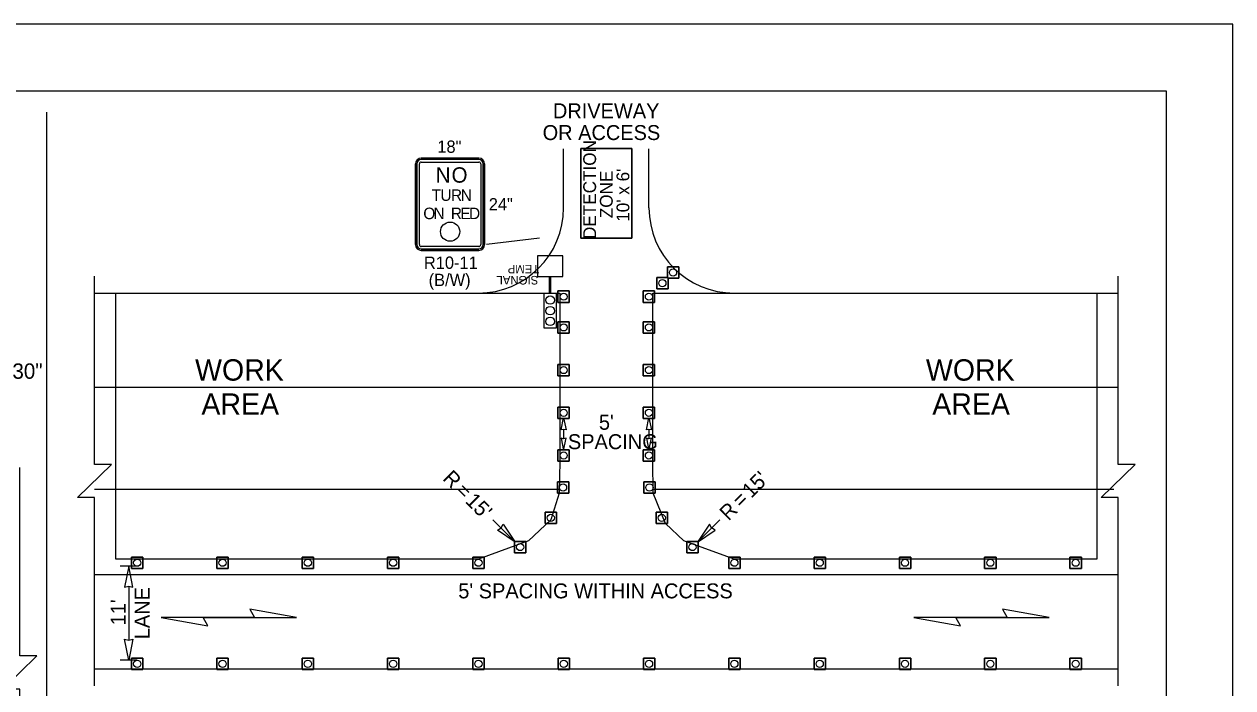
# Model space of a CAD drawing. Extents: x 99979.8 to 100075.7, y 99995 to 100010.7.
# Drawn here: x 100050.4 to 100056.06, y 100007.58 to 100010.69 of the extents above; entities that cross this region are included whole.
import ezdxf

# ---------------------------------------------------------------- set-up
doc = ezdxf.new("R2010")
doc.units = 0
for name, color, linetype in [('Default', 7, 'Continuous'), ('RD_ED_DrivewayEdge', 7, 'Continuous'), ('RD_ED_ShoulderPavedEdge', 7, 'Continuous'), ('RD_MK_LineEdgeWhite', 7, 'Continuous'), ('RD_MK_LineSkipCenter', 7, 'Continuous'), ('SH_GI_PlotLimits', 7, 'Continuous'), ('SH_GI_SheetBorder', 7, 'Continuous'), ('TR_SN_ConstructionSigns', 7, 'Continuous'), ('TR_WZ_TempSignal', 7, 'Continuous'), ('TR_WZ_TrafficCone', 7, 'Continuous'), ('TR_WZ_WorkAreaLabel', 7, 'Continuous'), ('TR_WZ_WorkZoneDetails', 7, 'Continuous'), ('TR_WZ_WorkZoneTextCurrent', 7, 'Continuous')]:
    doc.layers.add(name, color=color, linetype=linetype)

msp = doc.modelspace()

# ---------------------------------------------------------------- linework, layer by layer
at = {"layer": 'Default'}
msp.add_circle((100052.3926, 100009.7156), 0.045, dxfattribs=at)
at = {"layer": 'RD_ED_DrivewayEdge'}
for p, q in [((100052.925, 100009.8277), (100052.925, 100010.103)), ((100053.325, 100009.8277), (100053.325, 100010.103))]:
    msp.add_line(p, q, dxfattribs=at)
for centre, start, end in [((100052.525, 100009.8277), 270, 0), ((100053.725, 100009.8277), 180, 270)]:
    msp.add_arc(centre, 0.4, start, end, dxfattribs=at)
at = {"layer": 'RD_ED_ShoulderPavedEdge'}
for p, q in [((100050.725, 100009.4277), (100052.525, 100009.4277)), ((100053.725, 100009.4277), (100055.525, 100009.4277)), ((100050.725, 100007.6677), (100055.525, 100007.6677))]:
    msp.add_line(p, q, dxfattribs=at)
at = {"layer": 'RD_MK_LineEdgeWhite'}
for p, q in [((100050.725, 100008.9877), (100055.525, 100008.9877)), ((100055.525, 100008.1077), (100050.725, 100008.1077))]:
    msp.add_line(p, q, dxfattribs=at)
at = {"layer": 'RD_MK_LineSkipCenter'}
for points in [[(100052.9017, 100008.5077), (100050.725, 100008.5077)], [(100055.5043, 100008.5077), (100053.3483, 100008.5077)]]:
    msp.add_lwpolyline(points, dxfattribs=at)
at = {"layer": 'SH_GI_PlotLimits'}
msp.add_lwpolyline([(100039.0625, 99999.6875), (100056.0625, 99999.6875), (100056.0625, 100010.6875), (100039.0625, 100010.6875)], close=True, dxfattribs=at)
at = {"layer": 'SH_GI_SheetBorder'}
for p, q in [((100040, 100010.375), (100055.75, 100010.375)), ((100055.75, 100010.375), (100055.75, 100000))]:
    msp.add_line(p, q, dxfattribs=at)
at = {"layer": 'TR_SN_ConstructionSigns'}
for p, q in [((100052.2576, 100010.0598), (100052.5276, 100010.0598)), ((100052.5276, 100010.0598), (100052.2576, 100010.0598)), ((100052.5276, 100010.0598), (100052.2576, 100010.0598)), ((100052.5276, 100010.0531), (100052.2576, 100010.0531)), ((100052.2306, 100009.6548), (100052.2306, 100010.0328)), ((100052.2306, 100010.0328), (100052.2306, 100009.6548)), ((100052.2306, 100010.0328), (100052.2306, 100009.6548)), ((100052.2374, 100010.0328), (100052.2374, 100009.6548)), ((100052.2486, 100009.6548), (100052.2486, 100010.0328)), ((100052.2576, 100010.0418), (100052.5276, 100010.0418)), ((100052.5366, 100010.0328), (100052.5366, 100009.6548)), ((100052.5479, 100009.6548), (100052.5479, 100010.0328)), ((100052.5546, 100010.0328), (100052.5546, 100009.6548)), ((100052.5546, 100009.6548), (100052.5546, 100010.0328)), ((100052.5546, 100009.6548), (100052.5546, 100010.0328)), ((100052.5276, 100009.6458), (100052.2576, 100009.6458)), ((100052.2576, 100009.6346), (100052.5276, 100009.6346)), ((100052.5276, 100009.6278), (100052.2576, 100009.6278)), ((100052.2576, 100009.6278), (100052.5276, 100009.6278)), ((100052.2576, 100009.6278), (100052.5276, 100009.6278))]:
    msp.add_line(p, q, dxfattribs=at)
for centre, radius, start, end in [((100052.2576, 100010.0328), 0.027, 90, 180), ((100052.2576, 100010.0328), 0.027, 90, 180), ((100052.2576, 100010.0328), 0.027, 90, 180), ((100052.2576, 100010.0328), 0.0203, 90, 180), ((100052.5276, 100010.0328), 0.027, 0, 90), ((100052.5276, 100010.0328), 0.027, 0, 90), ((100052.5276, 100010.0328), 0.027, 0, 90), ((100052.5276, 100010.0328), 0.0203, 0, 90), ((100052.2576, 100010.0328), 0.009, 90, 180), ((100052.5276, 100010.0328), 0.009, 0, 90), ((100052.2576, 100009.6548), 0.027, 180, 270), ((100052.2576, 100009.6548), 0.027, 180, 270), ((100052.2576, 100009.6548), 0.027, 180, 270), ((100052.2576, 100009.6548), 0.0203, 180, 270), ((100052.2576, 100009.6548), 0.009, 180, 270), ((100052.5276, 100009.6548), 0.027, 270, 0), ((100052.5276, 100009.6548), 0.027, 270, 0), ((100052.5276, 100009.6548), 0.0203, 270, 0), ((100052.5276, 100009.6548), 0.009, 270, 0), ((100052.5276, 100009.6548), 0.027, 270, 0)]:
    msp.add_arc(centre, radius, start, end, dxfattribs=at)
at = {"layer": 'TR_WZ_TempSignal'}
for p, q in [((100052.9217, 100009.603), (100052.8017, 100009.603)), ((100052.8017, 100009.603), (100052.8017, 100009.5052)), ((100052.9217, 100009.5586), (100052.9217, 100009.603)), ((100052.9217, 100009.5497), (100052.9217, 100009.5586)), ((100052.9217, 100009.5052), (100052.9217, 100009.5497)), ((100052.8017, 100009.5052), (100052.9217, 100009.5052)), ((100052.8917, 100009.4252), (100052.8318, 100009.4252)), ((100052.8318, 100009.4252), (100052.8318, 100009.2655)), ((100052.8917, 100009.2655), (100052.8917, 100009.4252)), ((100052.8318, 100009.2655), (100052.8917, 100009.2655))]:
    msp.add_line(p, q, dxfattribs=at)
for points in [[(100052.8017, 100009.5052), (100052.9217, 100009.5052), (100052.9217, 100009.603), (100052.8017, 100009.603), (100052.8017, 100009.5052)], [(100052.8318, 100009.2655), (100052.8917, 100009.2655), (100052.8917, 100009.4252), (100052.8318, 100009.4252), (100052.8318, 100009.2655)]]:
    msp.add_lwpolyline(points, dxfattribs=at)
msp.add_lwpolyline([(100052.8642, 100009.4252), (100052.8592, 100009.4252), (100052.8592, 100009.5052), (100052.8642, 100009.5052)], close=True, dxfattribs=at)
for centre in [(100052.8617, 100009.3953), (100052.8617, 100009.3953), (100052.8617, 100009.3454), (100052.8617, 100009.3454), (100052.8617, 100009.2954), (100052.8617, 100009.2954)]:
    msp.add_circle(centre, 0.02, dxfattribs=at)
at = {"layer": 'TR_WZ_TrafficCone'}
for points in [[(100053.4115, 100009.5509), (100053.4115, 100009.4976), (100053.4649, 100009.4976), (100053.4649, 100009.5509), (100053.4115, 100009.5509)], [(100053.4649, 100009.5509), (100053.4649, 100009.4976), (100053.4115, 100009.4976), (100053.4115, 100009.5509), (100053.4649, 100009.5509)], [(100053.3615, 100009.5009), (100053.3615, 100009.4476), (100053.4149, 100009.4476), (100053.4149, 100009.5009), (100053.3615, 100009.5009)], [(100053.4149, 100009.5009), (100053.4149, 100009.4476), (100053.3615, 100009.4476), (100053.3615, 100009.5009), (100053.4149, 100009.5009)], [(100052.8983, 100009.4377), (100052.9517, 100009.4377), (100052.9517, 100009.3844), (100052.8983, 100009.3844), (100052.8983, 100009.4377)], [(100052.8983, 100009.3844), (100052.9517, 100009.3844), (100052.9517, 100009.4377), (100052.8983, 100009.4377), (100052.8983, 100009.3844)], [(100053.3516, 100009.4377), (100053.2982, 100009.4377), (100053.2982, 100009.3844), (100053.3516, 100009.3844), (100053.3516, 100009.4377)], [(100053.3516, 100009.3844), (100053.2982, 100009.3844), (100053.2982, 100009.4377), (100053.3516, 100009.4377), (100053.3516, 100009.3844)], [(100052.8983, 100009.2938), (100052.9517, 100009.2938), (100052.9517, 100009.2404), (100052.8983, 100009.2404), (100052.8983, 100009.2938)], [(100052.8983, 100009.2404), (100052.9517, 100009.2404), (100052.9517, 100009.2938), (100052.8983, 100009.2938), (100052.8983, 100009.2404)], [(100053.3516, 100009.2938), (100053.2982, 100009.2938), (100053.2982, 100009.2404), (100053.3516, 100009.2404), (100053.3516, 100009.2938)], [(100053.3516, 100009.2404), (100053.2982, 100009.2404), (100053.2982, 100009.2938), (100053.3516, 100009.2938), (100053.3516, 100009.2404)], [(100052.8983, 100009.0938), (100052.9517, 100009.0938), (100052.9517, 100009.0404), (100052.8983, 100009.0404), (100052.8983, 100009.0938)], [(100052.8983, 100009.0404), (100052.9517, 100009.0404), (100052.9517, 100009.0938), (100052.8983, 100009.0938), (100052.8983, 100009.0404)], [(100053.3516, 100009.0938), (100053.2982, 100009.0938), (100053.2982, 100009.0404), (100053.3516, 100009.0404), (100053.3516, 100009.0938)], [(100053.3516, 100009.0404), (100053.2982, 100009.0404), (100053.2982, 100009.0938), (100053.3516, 100009.0938), (100053.3516, 100009.0404)], [(100052.8983, 100008.8938), (100052.9517, 100008.8938), (100052.9517, 100008.8404), (100052.8983, 100008.8404), (100052.8983, 100008.8938)], [(100052.8983, 100008.8404), (100052.9517, 100008.8404), (100052.9517, 100008.8938), (100052.8983, 100008.8938), (100052.8983, 100008.8404)], [(100053.3516, 100008.8938), (100053.2982, 100008.8938), (100053.2982, 100008.8404), (100053.3516, 100008.8404), (100053.3516, 100008.8938)], [(100053.3516, 100008.8404), (100053.2982, 100008.8404), (100053.2982, 100008.8938), (100053.3516, 100008.8938), (100053.3516, 100008.8404)], [(100052.8983, 100008.6938), (100052.9517, 100008.6938), (100052.9517, 100008.6404), (100052.8983, 100008.6404), (100052.8983, 100008.6938)], [(100052.8983, 100008.6404), (100052.9517, 100008.6404), (100052.9517, 100008.6938), (100052.8983, 100008.6938), (100052.8983, 100008.6404)], [(100053.3516, 100008.6938), (100053.2982, 100008.6938), (100053.2982, 100008.6404), (100053.3516, 100008.6404), (100053.3516, 100008.6938)], [(100053.3516, 100008.6404), (100053.2982, 100008.6404), (100053.2982, 100008.6938), (100053.3516, 100008.6938), (100053.3516, 100008.6404)], [(100052.8956, 100008.5438), (100052.9489, 100008.5438), (100052.9489, 100008.4904), (100052.8956, 100008.4904), (100052.8956, 100008.5438)], [(100052.8956, 100008.4904), (100052.9489, 100008.4904), (100052.9489, 100008.5438), (100052.8956, 100008.5438), (100052.8956, 100008.4904)], [(100053.3543, 100008.5438), (100053.301, 100008.5438), (100053.301, 100008.4904), (100053.3543, 100008.4904), (100053.3543, 100008.5438)], [(100053.3543, 100008.4904), (100053.301, 100008.4904), (100053.301, 100008.5438), (100053.3543, 100008.5438), (100053.3543, 100008.4904)], [(100052.838, 100008.4015), (100052.8914, 100008.4015), (100052.8914, 100008.3482), (100052.838, 100008.3482), (100052.838, 100008.4015)], [(100052.838, 100008.3482), (100052.8914, 100008.3482), (100052.8914, 100008.4015), (100052.838, 100008.4015), (100052.838, 100008.3482)], [(100053.4119, 100008.4015), (100053.3585, 100008.4015), (100053.3585, 100008.3482), (100053.4119, 100008.3482), (100053.4119, 100008.4015)], [(100053.4119, 100008.3482), (100053.3585, 100008.3482), (100053.3585, 100008.4015), (100053.4119, 100008.4015), (100053.4119, 100008.3482)], [(100052.6943, 100008.2647), (100052.7477, 100008.2647), (100052.7477, 100008.2114), (100052.6943, 100008.2114), (100052.6943, 100008.2647)], [(100052.6943, 100008.2114), (100052.7477, 100008.2114), (100052.7477, 100008.2647), (100052.6943, 100008.2647), (100052.6943, 100008.2114)], [(100053.5556, 100008.2647), (100053.5023, 100008.2647), (100053.5023, 100008.2114), (100053.5556, 100008.2114), (100053.5556, 100008.2647)], [(100053.5556, 100008.2114), (100053.5023, 100008.2114), (100053.5023, 100008.2647), (100053.5556, 100008.2647), (100053.5556, 100008.2114)], [(100050.899, 100008.191), (100050.9523, 100008.191), (100050.9523, 100008.1377), (100050.899, 100008.1377), (100050.899, 100008.191)], [(100050.899, 100008.1377), (100050.9523, 100008.1377), (100050.9523, 100008.191), (100050.899, 100008.191), (100050.899, 100008.1377)], [(100051.299, 100008.191), (100051.3523, 100008.191), (100051.3523, 100008.1377), (100051.299, 100008.1377), (100051.299, 100008.191)], [(100051.299, 100008.1377), (100051.3523, 100008.1377), (100051.3523, 100008.191), (100051.299, 100008.191), (100051.299, 100008.1377)], [(100051.699, 100008.191), (100051.7523, 100008.191), (100051.7523, 100008.1377), (100051.699, 100008.1377), (100051.699, 100008.191)], [(100051.699, 100008.1377), (100051.7523, 100008.1377), (100051.7523, 100008.191), (100051.699, 100008.191), (100051.699, 100008.1377)], [(100052.099, 100008.191), (100052.1523, 100008.191), (100052.1523, 100008.1377), (100052.099, 100008.1377), (100052.099, 100008.191)], [(100052.099, 100008.1377), (100052.1523, 100008.1377), (100052.1523, 100008.191), (100052.099, 100008.191), (100052.099, 100008.1377)], [(100052.499, 100008.191), (100052.5523, 100008.191), (100052.5523, 100008.1377), (100052.499, 100008.1377), (100052.499, 100008.191)], [(100052.499, 100008.1377), (100052.5523, 100008.1377), (100052.5523, 100008.191), (100052.499, 100008.191), (100052.499, 100008.1377)], [(100053.699, 100008.191), (100053.7523, 100008.191), (100053.7523, 100008.1377), (100053.699, 100008.1377), (100053.699, 100008.191)], [(100053.699, 100008.1377), (100053.7523, 100008.1377), (100053.7523, 100008.191), (100053.699, 100008.191), (100053.699, 100008.1377)], [(100053.699, 100008.191), (100053.7523, 100008.191), (100053.7523, 100008.1377), (100053.699, 100008.1377), (100053.699, 100008.191)], [(100053.699, 100008.1377), (100053.7523, 100008.1377), (100053.7523, 100008.191), (100053.699, 100008.191), (100053.699, 100008.1377)], [(100054.099, 100008.191), (100054.1523, 100008.191), (100054.1523, 100008.1377), (100054.099, 100008.1377), (100054.099, 100008.191)], [(100054.099, 100008.1377), (100054.1523, 100008.1377), (100054.1523, 100008.191), (100054.099, 100008.191), (100054.099, 100008.1377)], [(100054.499, 100008.191), (100054.5523, 100008.191), (100054.5523, 100008.1377), (100054.499, 100008.1377), (100054.499, 100008.191)], [(100054.499, 100008.1377), (100054.5523, 100008.1377), (100054.5523, 100008.191), (100054.499, 100008.191), (100054.499, 100008.1377)], [(100054.899, 100008.191), (100054.9523, 100008.191), (100054.9523, 100008.1377), (100054.899, 100008.1377), (100054.899, 100008.191)], [(100054.899, 100008.1377), (100054.9523, 100008.1377), (100054.9523, 100008.191), (100054.899, 100008.191), (100054.899, 100008.1377)], [(100055.299, 100008.191), (100055.3523, 100008.191), (100055.3523, 100008.1377), (100055.299, 100008.1377), (100055.299, 100008.191)], [(100055.299, 100008.1377), (100055.3523, 100008.1377), (100055.3523, 100008.191), (100055.299, 100008.191), (100055.299, 100008.1377)], [(100050.899, 100007.7177), (100050.9524, 100007.7177), (100050.9524, 100007.6644), (100050.899, 100007.6644), (100050.899, 100007.7177)], [(100050.899, 100007.6644), (100050.9524, 100007.6644), (100050.9524, 100007.7177), (100050.899, 100007.7177), (100050.899, 100007.6644)], [(100051.299, 100007.7177), (100051.3524, 100007.7177), (100051.3524, 100007.6644), (100051.299, 100007.6644), (100051.299, 100007.7177)], [(100051.299, 100007.6644), (100051.3524, 100007.6644), (100051.3524, 100007.7177), (100051.299, 100007.7177), (100051.299, 100007.6644)], [(100051.699, 100007.7177), (100051.7523, 100007.7177), (100051.7523, 100007.6644), (100051.699, 100007.6644), (100051.699, 100007.7177)], [(100051.699, 100007.6644), (100051.7523, 100007.6644), (100051.7523, 100007.7177), (100051.699, 100007.7177), (100051.699, 100007.6644)], [(100052.099, 100007.7177), (100052.1523, 100007.7177), (100052.1523, 100007.6644), (100052.099, 100007.6644), (100052.099, 100007.7177)], [(100052.099, 100007.6644), (100052.1523, 100007.6644), (100052.1523, 100007.7177), (100052.099, 100007.7177), (100052.099, 100007.6644)], [(100052.499, 100007.7177), (100052.5523, 100007.7177), (100052.5523, 100007.6644), (100052.499, 100007.6644), (100052.499, 100007.7177)], [(100052.499, 100007.6644), (100052.5523, 100007.6644), (100052.5523, 100007.7177), (100052.499, 100007.7177), (100052.499, 100007.6644)], [(100052.899, 100007.7177), (100052.9523, 100007.7177), (100052.9523, 100007.6644), (100052.899, 100007.6644), (100052.899, 100007.7177)], [(100052.899, 100007.6644), (100052.9523, 100007.6644), (100052.9523, 100007.7177), (100052.899, 100007.7177), (100052.899, 100007.6644)], [(100053.299, 100007.7177), (100053.3523, 100007.7177), (100053.3523, 100007.6644), (100053.299, 100007.6644), (100053.299, 100007.7177)], [(100053.299, 100007.6644), (100053.3523, 100007.6644), (100053.3523, 100007.7177), (100053.299, 100007.7177), (100053.299, 100007.6644)], [(100053.699, 100007.7177), (100053.7523, 100007.7177), (100053.7523, 100007.6644), (100053.699, 100007.6644), (100053.699, 100007.7177)], [(100053.699, 100007.6644), (100053.7523, 100007.6644), (100053.7523, 100007.7177), (100053.699, 100007.7177), (100053.699, 100007.6644)], [(100054.099, 100007.7177), (100054.1523, 100007.7177), (100054.1523, 100007.6644), (100054.099, 100007.6644), (100054.099, 100007.7177)], [(100054.099, 100007.6644), (100054.1523, 100007.6644), (100054.1523, 100007.7177), (100054.099, 100007.7177), (100054.099, 100007.6644)], [(100054.499, 100007.7177), (100054.5523, 100007.7177), (100054.5523, 100007.6644), (100054.499, 100007.6644), (100054.499, 100007.7177)], [(100054.499, 100007.6644), (100054.5523, 100007.6644), (100054.5523, 100007.7177), (100054.499, 100007.7177), (100054.499, 100007.6644)], [(100054.899, 100007.7177), (100054.9523, 100007.7177), (100054.9523, 100007.6644), (100054.899, 100007.6644), (100054.899, 100007.7177)], [(100054.899, 100007.6644), (100054.9523, 100007.6644), (100054.9523, 100007.7177), (100054.899, 100007.7177), (100054.899, 100007.6644)], [(100055.299, 100007.7177), (100055.3523, 100007.7177), (100055.3523, 100007.6644), (100055.299, 100007.6644), (100055.299, 100007.7177)], [(100055.299, 100007.6644), (100055.3523, 100007.6644), (100055.3523, 100007.7177), (100055.299, 100007.7177), (100055.299, 100007.6644)]]:
    msp.add_lwpolyline(points, dxfattribs=at)
for centre in [(100053.4382, 100009.5243), (100053.3882, 100009.4743), (100052.925, 100009.411), (100053.3249, 100009.411), (100052.925, 100009.2671), (100053.3249, 100009.2671), (100052.925, 100009.0671), (100053.3249, 100009.0671), (100052.925, 100008.8671), (100053.3249, 100008.8671), (100052.925, 100008.6671), (100053.3249, 100008.6671), (100052.9223, 100008.5171), (100053.3276, 100008.5171), (100052.8647, 100008.3748), (100053.3852, 100008.3748), (100052.721, 100008.238), (100053.5289, 100008.238), (100050.9257, 100008.1644), (100051.3257, 100008.1644), (100051.7257, 100008.1644), (100052.1257, 100008.1644), (100052.5257, 100008.1644), (100053.7257, 100008.1644), (100053.7257, 100008.1644), (100054.1257, 100008.1644), (100054.5257, 100008.1644), (100054.9257, 100008.1644), (100055.3257, 100008.1644), (100050.9257, 100007.691), (100051.3257, 100007.691), (100051.7257, 100007.691), (100052.1257, 100007.691), (100052.5257, 100007.691), (100052.9257, 100007.691), (100053.3257, 100007.691), (100053.7257, 100007.691), (100054.1257, 100007.691), (100054.5257, 100007.691), (100054.9257, 100007.691), (100055.3257, 100007.691)]:
    msp.add_circle(centre, 0.0167, dxfattribs=at)
at = {"layer": 'TR_WZ_WorkZoneDetails'}
for p, q in [((100050.5, 100010.275), (100050.5, 100001.2259)), ((100052.8117, 100009.6848), (100052.5638, 100009.6552)), ((100052.925, 100008.7893), (100052.925, 100008.7449)), ((100053.325, 100008.7893), (100053.325, 100008.7449)), ((100052.6977, 100008.2614), (100052.593, 100008.366)), ((100053.5523, 100008.2614), (100053.657, 100008.366)), ((100050.9257, 100008.1477), (100050.8457, 100008.1477)), ((100050.8857, 100008.054), (100050.8857, 100007.8014)), ((100051.4761, 100007.9077), (100051.235, 100007.9077)), ((100051.235, 100007.9077), (100051.4761, 100007.9077)), ((100055.0052, 100007.9077), (100054.7641, 100007.9077)), ((100054.7641, 100007.9077), (100055.0052, 100007.9077)), ((100050.9257, 100007.7077), (100050.8457, 100007.7077))]:
    msp.add_line(p, q, dxfattribs=at)
for points in [[(100053.005, 100009.6848), (100053.005, 100010.1048), (100053.245, 100010.1048), (100053.245, 100009.6848), (100053.005, 100009.6848)], [(100053.245, 100009.6848), (100053.245, 100010.1048), (100053.005, 100010.1048), (100053.005, 100009.6848), (100053.245, 100009.6848)], [(100050.725, 100007.5877), (100050.725, 100008.4703), (100050.645, 100008.4703), (100050.805, 100008.6251), (100050.725, 100008.6251), (100050.725, 100009.5077)], [(100055.525, 100007.5877), (100055.525, 100008.4703), (100055.445, 100008.4703), (100055.605, 100008.6251), (100055.525, 100008.6251), (100055.525, 100009.5077)], [(100050.375, 100006.6904), (100050.375, 100007.573), (100050.295, 100007.573), (100050.455, 100007.7279), (100050.375, 100007.7279), (100050.375, 100008.6105)]]:
    msp.add_lwpolyline(points, dxfattribs=at)
for points in [[(100052.9075, 100009.4277), (100052.9075, 100008.8402), (100052.9075, 100008.6402), (100052.9048, 100008.4902), (100052.9048, 100008.4902), (100052.9048, 100008.4902), (100052.8647, 100008.3655), (100052.8647, 100008.3655), (100052.8647, 100008.3655), (100052.7607, 100008.2677), (100052.5257, 100008.181), (100051.5503, 100008.181), (100051.1882, 100008.181), (100050.825, 100008.181), (100050.825, 100009.4277)], [(100055.425, 100009.4277), (100055.425, 100008.6402), (100055.425, 100008.181), (100054.5265, 100008.181), (100054.5265, 100008.181), (100054.5265, 100008.181), (100053.7244, 100008.181), (100053.7244, 100008.181), (100053.7244, 100008.181), (100053.489, 100008.2677), (100053.4028, 100008.348), (100053.3452, 100008.4902), (100053.3425, 100008.6402), (100053.3425, 100008.8402), (100053.3425, 100009.4277)], [(100052.925, 100008.8438), (100052.9362, 100008.7866), (100052.925, 100008.7893), (100052.9138, 100008.7866)], [(100053.325, 100008.8438), (100053.3362, 100008.7866), (100053.325, 100008.7893), (100053.3138, 100008.7866)], [(100052.925, 100008.6904), (100052.9362, 100008.7476), (100052.925, 100008.7449), (100052.9138, 100008.7476)], [(100053.325, 100008.6904), (100053.3362, 100008.7476), (100053.325, 100008.7449), (100053.3138, 100008.7476)], [(100052.6977, 100008.2614), (100052.6146, 100008.3173), (100052.6314, 100008.3277), (100052.6418, 100008.3445)], [(100053.5523, 100008.2614), (100053.6354, 100008.3173), (100053.6186, 100008.3277), (100053.6082, 100008.3445)], [(100050.8857, 100008.1477), (100050.8664, 100008.0494), (100050.8857, 100008.054), (100050.905, 100008.0494)], [(100051.0385, 100007.9077), (100051.2573, 100007.8691), (100051.235, 100007.9077)], [(100051.6727, 100007.9077), (100051.4539, 100007.9463), (100051.4761, 100007.9077)], [(100054.5675, 100007.9077), (100054.7864, 100007.8691), (100054.7641, 100007.9077)], [(100055.2017, 100007.9077), (100054.9829, 100007.9463), (100055.0052, 100007.9077)], [(100050.8857, 100007.7077), (100050.8664, 100007.806), (100050.8857, 100007.8014), (100050.905, 100007.806)]]:
    msp.add_lwpolyline(points, close=True, dxfattribs=at)

# ---------------------------------------------------------------- texts
at = {"layer": 'Default'}
for s, height, p in [('N', 0.072, (100052.3253, 100009.9451)), ('O', 0.072, (100052.3995, 100009.9451)), ('T', 0.054, (100052.3061, 100009.8596)), ('U', 0.054, (100052.3474, 100009.8596)), ('R', 0.054, (100052.3968, 100009.8596)), ('N', 0.054, (100052.4424, 100009.8596)), ('O', 0.054, (100052.2671, 100009.7741)), ('N', 0.054, (100052.3152, 100009.7741)), ('R', 0.054, (100052.3961, 100009.7741)), ('E', 0.054, (100052.4404, 100009.7741)), ('D', 0.054, (100052.4814, 100009.7741))]:
    msp.add_text(s, height=height, dxfattribs=at).set_placement(p)
at = {"layer": 'TR_SN_ConstructionSigns'}
for s, height, p in [('18"', 0.0576, (100052.3328, 100010.085)), ('24"', 0.0576, (100052.574, 100009.815)), ('R10-11', 0.0576, (100052.2698, 100009.5414)), ('(B/W)', 0.0576, (100052.2921, 100009.4608)), ('30"', 0.072, (100050.3406, 100009.0263))]:
    msp.add_text(s, height=height, rotation=360, dxfattribs=at).set_placement(p)
at = {"layer": 'TR_WZ_TempSignal'}
for s, p in [('TEMP', (100052.8111, 100009.5601)), ('SIGNAL', (100052.8062, 100009.5081))]:
    msp.add_text(s, height=0.04, rotation=180, dxfattribs=at).set_placement(p)
at = {"layer": 'TR_WZ_WorkAreaLabel'}
for s, p in [('WORK', (100051.197, 100009.0177)), ('WORK', (100054.6236, 100009.0177)), ('AREA', (100051.2267, 100008.8577)), ('AREA', (100054.6533, 100008.8577))]:
    msp.add_text(s, height=0.1, rotation=360, dxfattribs=at).set_placement(p)
at = {"layer": 'TR_WZ_WorkZoneDetails'}
for s, p in [('DETECTION', (100053.077, 100009.681)), ('ZONE', (100053.155, 100009.7786)), ("10' x 6'", (100053.233, 100009.7618))]:
    msp.add_text(s, height=0.06, rotation=90, dxfattribs=at).set_placement(p)
at = {"layer": 'TR_WZ_WorkZoneTextCurrent'}
for s, p in [('DRIVEWAY', (100052.8748, 100010.2468)), ('OR ACCESS', (100052.8266, 100010.1448)), ("5'", (100053.0904, 100008.7876)), ('SPACING', (100052.945, 100008.6966)), ("5' SPACING WITHIN ACCESS", (100052.431, 100007.9977))]:
    msp.add_text(s, height=0.07, dxfattribs=at).set_placement(p)
for s, rotation, p in [('R', 315, (100052.3542, 100008.5553)), ("15'", 45, (100053.8042, 100008.4637)), ('=', 315, (100052.4134, 100008.4961)), ("15'", 315, (100052.4603, 100008.4493)), ('=', 45, (100053.7574, 100008.4169)), ('R', 45, (100053.6982, 100008.3577)), ('LANE', 90, (100050.9837, 100007.8062)), ("11'", 90, (100050.8717, 100007.8709))]:
    msp.add_text(s, height=0.07, rotation=rotation, dxfattribs=at).set_placement(p)

doc.saveas('drawing.dxf')
